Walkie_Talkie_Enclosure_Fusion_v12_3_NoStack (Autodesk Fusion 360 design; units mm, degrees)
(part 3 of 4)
sketch "Volume Up Switch Side Rail Sketch (1)" plane through (0, 0, 0) normal (0, 0, 1) x axis (1, 0, 0)
  line L1 (-32.325, 27.55) -> (-36.675, 27.55)
  line L2 (-32.025, 28.05) -> (-32.025, 27.85)
  line L3 (-36.675, 28.35) -> (-32.325, 28.35)
  line L4 (-36.975, 27.85) -> (-36.975, 28.05)
  arc A1 centre (-32.325, 27.85) radius 0.3 clockwise from (-32.025, 27.85) to (-32.325, 27.55)
  arc A2 centre (-32.325, 28.05) radius 0.3 clockwise from (-32.325, 28.35) to (-32.025, 28.05)
  arc A3 centre (-36.675, 28.05) radius 0.3 clockwise from (-36.975, 28.05) to (-36.675, 28.35)
  arc A4 centre (-36.675, 27.85) radius 0.3 clockwise from (-36.675, 27.55) to (-36.975, 27.85)
extrude "Extrude29" add sketch "Volume Up Switch Side Rail Sketch (1)" blind 7.01 from offset 12
sketch "Volume Up Switch Actuator Shoulder Sketch" plane through (0, 0, 0) normal (0, 0, 1) x axis (1, 0, 0)
  line L1 (-37.22, 17.65) -> (-37.28, 17.65)
  line L2 (-37, 28.13) -> (-37, 17.87)
  line L3 (-37.28, 28.35) -> (-37.22, 28.35)
  line L4 (-37.5, 17.87) -> (-37.5, 28.13)
  arc A1 centre (-37.22, 17.87) radius 0.22 clockwise from (-37, 17.87) to (-37.22, 17.65)
  arc A2 centre (-37.22, 28.13) radius 0.22 clockwise from (-37.22, 28.35) to (-37, 28.13)
  arc A3 centre (-37.28, 28.13) radius 0.22 clockwise from (-37.5, 28.13) to (-37.28, 28.35)
  arc A4 centre (-37.28, 17.87) radius 0.22 clockwise from (-37.28, 17.65) to (-37.5, 17.87)
extrude "Extrude30" add sketch "Volume Up Switch Actuator Shoulder Sketch" blind 7.01 from offset 12
sketch "Volume Up Actuator Passage Sketch" plane through (0, 0, 0) normal (1, 0, 0) x axis (0, 0, -1)
  line L1 (-14.4, 21.6) -> (-16, 21.6)
  line L2 (-13.8, 23.8) -> (-13.8, 22.2)
  line L3 (-16, 24.4) -> (-14.4, 24.4)
  line L4 (-16.6, 22.2) -> (-16.6, 23.8)
  arc A1 centre (-14.4, 22.2) radius 0.6 clockwise from (-13.8, 22.2) to (-14.4, 21.6)
  arc A2 centre (-14.4, 23.8) radius 0.6 clockwise from (-14.4, 24.4) to (-13.8, 23.8)
  arc A3 centre (-16, 23.8) radius 0.6 clockwise from (-16.6, 23.8) to (-16, 24.4)
  arc A4 centre (-16, 22.2) radius 0.6 clockwise from (-16, 21.6) to (-16.6, 22.2)
extrude "Extrude31" cut sketch "Volume Up Actuator Passage Sketch" blind -4.2 (= "-( 4.20 mm )") from offset -35.8
sketch "Volume Down Internal Switch Body Clearance Sketch" plane through (0, 0, 0) normal (1, 0, 0) x axis (0, 0, -1)
  line L1 (-8.49, -11.35) -> (-18.01, -11.35)
  line L2 (-8.04, -1.1) -> (-8.04, -10.9)
  line L3 (-18.01, -0.65) -> (-8.49, -0.65)
  line L4 (-18.46, -10.9) -> (-18.46, -1.1)
  arc A1 centre (-8.49, -10.9) radius 0.45 clockwise from (-8.04, -10.9) to (-8.49, -11.35)
  arc A2 centre (-8.49, -1.1) radius 0.45 clockwise from (-8.49, -0.65) to (-8.04, -1.1)
  arc A3 centre (-18.01, -1.1) radius 0.45 clockwise from (-18.46, -1.1) to (-18.01, -0.65)
  arc A4 centre (-18.01, -10.9) radius 0.45 clockwise from (-18.01, -11.35) to (-18.46, -10.9)
extrude "Extrude32" cut sketch "Volume Down Internal Switch Body Clearance Sketch" blind -5.1 (= "-( 5.10 mm )") from offset -31.9
sketch "Volume Down Switch Cage Anchor Sketch" plane through (0, 0, 0) normal (0, 0, 1) x axis (1, 0, 0)
  line L1 (-31.5, -11.55) -> (-32, -11.55)
  line L2 (-31.15, -10.7) -> (-31.15, -11.2)
  line L3 (-32, -10.35) -> (-31.5, -10.35)
  line L4 (-32.35, -11.2) -> (-32.35, -10.7)
  arc A1 centre (-31.5, -11.2) radius 0.35 clockwise from (-31.15, -11.2) to (-31.5, -11.55)
  arc A2 centre (-31.5, -10.7) radius 0.35 clockwise from (-31.5, -10.35) to (-31.15, -10.7)
  arc A3 centre (-32, -10.7) radius 0.35 clockwise from (-32.35, -10.7) to (-32, -10.35)
  arc A4 centre (-32, -11.2) radius 0.35 clockwise from (-32, -11.55) to (-32.35, -11.2)
extrude "Extrude33" add sketch "Volume Down Switch Cage Anchor Sketch" blind 2.99 from offset 18.91
sketch "Volume Down Switch Cage Anchor Sketch (1)" plane through (0, 0, 0) normal (0, 0, 1) x axis (1, 0, 0)
  line L1 (-31.5, -1.65) -> (-32, -1.65)
  line L2 (-31.15, -0.8) -> (-31.15, -1.3)
  line L3 (-32, -0.45) -> (-31.5, -0.45)
  line L4 (-32.35, -1.3) -> (-32.35, -0.8)
  arc A1 centre (-31.5, -1.3) radius 0.35 clockwise from (-31.15, -1.3) to (-31.5, -1.65)
  arc A2 centre (-31.5, -0.8) radius 0.35 clockwise from (-31.5, -0.45) to (-31.15, -0.8)
  arc A3 centre (-32, -0.8) radius 0.35 clockwise from (-32.35, -0.8) to (-32, -0.45)
  arc A4 centre (-32, -1.3) radius 0.35 clockwise from (-32, -1.65) to (-32.35, -1.3)
extrude "Extrude34" add sketch "Volume Down Switch Cage Anchor Sketch (1)" blind 2.99 from offset 18.91
sketch "Volume Down Switch Roof Sketch" plane through (0, 0, 0) normal (0, 0, 1) x axis (1, 0, 0)
  line L1 (-31.55, -11.35) -> (-36.65, -11.35)
  line L2 (-31.1, -1.1) -> (-31.1, -10.9)
  line L3 (-36.65, -0.65) -> (-31.55, -0.65)
  line L4 (-37.1, -10.9) -> (-37.1, -1.1)
  arc A1 centre (-31.55, -10.9) radius 0.45 clockwise from (-31.1, -10.9) to (-31.55, -11.35)
  arc A2 centre (-31.55, -1.1) radius 0.45 clockwise from (-31.55, -0.65) to (-31.1, -1.1)
  arc A3 centre (-36.65, -1.1) radius 0.45 clockwise from (-37.1, -1.1) to (-36.65, -0.65)
  arc A4 centre (-36.65, -10.9) radius 0.45 clockwise from (-36.65, -11.35) to (-37.1, -10.9)
extrude "Extrude35" add sketch "Volume Down Switch Roof Sketch" blind 0.55 from offset 18.46
sketch "Volume Down Switch Inward Backstop Sketch" plane through (0, 0, 0) normal (0, 0, 1) x axis (1, 0, 0)
  line L1 (-31.65, -11.35) -> (-31.85, -11.35)
  line L2 (-31.3, -1) -> (-31.3, -11)
  line L3 (-31.85, -0.65) -> (-31.65, -0.65)
  line L4 (-32.2, -11) -> (-32.2, -1)
  arc A1 centre (-31.65, -11) radius 0.35 clockwise from (-31.3, -11) to (-31.65, -11.35)
  arc A2 centre (-31.65, -1) radius 0.35 clockwise from (-31.65, -0.65) to (-31.3, -1)
  arc A3 centre (-31.85, -1) radius 0.35 clockwise from (-32.2, -1) to (-31.85, -0.65)
  arc A4 centre (-31.85, -11) radius 0.35 clockwise from (-31.85, -11.35) to (-32.2, -11)
extrude "Extrude36" add sketch "Volume Down Switch Inward Backstop Sketch" blind 7.01 from offset 12
sketch "Volume Down Switch Side Rail Sketch" plane through (0, 0, 0) normal (0, 0, 1) x axis (1, 0, 0)
  line L1 (-32.325, -11.35) -> (-36.675, -11.35)
  line L2 (-32.025, -10.85) -> (-32.025, -11.05)
  line L3 (-36.675, -10.55) -> (-32.325, -10.55)
  line L4 (-36.975, -11.05) -> (-36.975, -10.85)
  arc A1 centre (-32.325, -11.05) radius 0.3 clockwise from (-32.025, -11.05) to (-32.325, -11.35)
  arc A2 centre (-32.325, -10.85) radius 0.3 clockwise from (-32.325, -10.55) to (-32.025, -10.85)
  arc A3 centre (-36.675, -10.85) radius 0.3 clockwise from (-36.975, -10.85) to (-36.675, -10.55)
  arc A4 centre (-36.675, -11.05) radius 0.3 clockwise from (-36.675, -11.35) to (-36.975, -11.05)
extrude "Extrude37" add sketch "Volume Down Switch Side Rail Sketch" blind 7.01 from offset 12
sketch "Volume Down Switch Side Rail Sketch (1)" plane through (0, 0, 0) normal (0, 0, 1) x axis (1, 0, 0)
  line L1 (-32.325, -1.45) -> (-36.675, -1.45)
  line L2 (-32.025, -0.95) -> (-32.025, -1.15)
  line L3 (-36.675, -0.65) -> (-32.325, -0.65)
  line L4 (-36.975, -1.15) -> (-36.975, -0.95)
  arc A1 centre (-32.325, -1.15) radius 0.3 clockwise from (-32.025, -1.15) to (-32.325, -1.45)
  arc A2 centre (-32.325, -0.95) radius 0.3 clockwise from (-32.325, -0.65) to (-32.025, -0.95)
  arc A3 centre (-36.675, -0.95) radius 0.3 clockwise from (-36.975, -0.95) to (-36.675, -0.65)
  arc A4 centre (-36.675, -1.15) radius 0.3 clockwise from (-36.675, -1.45) to (-36.975, -1.15)
extrude "Extrude38" add sketch "Volume Down Switch Side Rail Sketch (1)" blind 7.01 from offset 12
sketch "Volume Down Switch Actuator Shoulder Sketch" plane through (0, 0, 0) normal (0, 0, 1) x axis (1, 0, 0)
  line L1 (-37.22, -11.35) -> (-37.28, -11.35)
  line L2 (-37, -0.87) -> (-37, -11.13)
  line L3 (-37.28, -0.65) -> (-37.22, -0.65)
  line L4 (-37.5, -11.13) -> (-37.5, -0.87)
  arc A1 centre (-37.22, -11.13) radius 0.22 clockwise from (-37, -11.13) to (-37.22, -11.35)
  arc A2 centre (-37.22, -0.87) radius 0.22 clockwise from (-37.22, -0.65) to (-37, -0.87)
  arc A3 centre (-37.28, -0.87) radius 0.22 clockwise from (-37.5, -0.87) to (-37.28, -0.65)
  arc A4 centre (-37.28, -11.13) radius 0.22 clockwise from (-37.28, -11.35) to (-37.5, -11.13)
extrude "Extrude39" add sketch "Volume Down Switch Actuator Shoulder Sketch" blind 7.01 from offset 12
sketch "Volume Down Actuator Passage Sketch" plane through (0, 0, 0) normal (1, 0, 0) x axis (0, 0, -1)
  line L1 (-14.4, -7.4) -> (-16, -7.4)
  line L2 (-13.8, -5.2) -> (-13.8, -6.8)
  line L3 (-16, -4.6) -> (-14.4, -4.6)
  line L4 (-16.6, -6.8) -> (-16.6, -5.2)
  arc A1 centre (-14.4, -6.8) radius 0.6 clockwise from (-13.8, -6.8) to (-14.4, -7.4)
  arc A2 centre (-14.4, -5.2) radius 0.6 clockwise from (-14.4, -4.6) to (-13.8, -5.2)
  arc A3 centre (-16, -5.2) radius 0.6 clockwise from (-16.6, -5.2) to (-16, -4.6)
  arc A4 centre (-16, -6.8) radius 0.6 clockwise from (-16, -7.4) to (-16.6, -6.8)
extrude "Extrude40" cut sketch "Volume Down Actuator Passage Sketch" blind -4.2 (= "-( 4.20 mm )") from offset -35.8
sketch "PCB Rear Edge Clip Trunk Sketch" plane through (0, 0, 0) normal (0, 0, 1) x axis (1, 0, 0)
  line L1 (-30.95, -45.04) -> (-31.65, -45.04)
  line L2 (-30.4, -39.59) -> (-30.4, -44.49)
  line L3 (-31.65, -39.04) -> (-30.95, -39.04)
  line L4 (-32.2, -44.49) -> (-32.2, -39.59)
  arc A1 centre (-30.95, -44.49) radius 0.55 clockwise from (-30.4, -44.49) to (-30.95, -45.04)
  arc A2 centre (-30.95, -39.59) radius 0.55 clockwise from (-30.95, -39.04) to (-30.4, -39.59)
  arc A3 centre (-31.65, -39.59) radius 0.55 clockwise from (-32.2, -39.59) to (-31.65, -39.04)
  arc A4 centre (-31.65, -44.49) radius 0.55 clockwise from (-31.65, -45.04) to (-32.2, -44.49)
extrude "Extrude41" add sketch "PCB Rear Edge Clip Trunk Sketch" blind 7.24 from offset 14.56
sketch "PCB Rear Substrate Ledge Sketch" plane through (0, 0, 0) normal (0, 0, 1) x axis (1, 0, 0)
  line L1 (-28.1, -45.04) -> (-31, -45.04)
  line L2 (-27.45, -39.69) -> (-27.45, -44.39)
  line L3 (-31, -39.04) -> (-28.1, -39.04)
  line L4 (-31.65, -44.39) -> (-31.65, -39.69)
  arc A1 centre (-28.1, -44.39) radius 0.65 clockwise from (-27.45, -44.39) to (-28.1, -45.04)
  arc A2 centre (-28.1, -39.69) radius 0.65 clockwise from (-28.1, -39.04) to (-27.45, -39.69)
  arc A3 centre (-31, -39.69) radius 0.65 clockwise from (-31.65, -39.69) to (-31, -39.04)
  arc A4 centre (-31, -44.39) radius 0.65 clockwise from (-31, -45.04) to (-31.65, -44.39)
extrude "Extrude42" add sketch "PCB Rear Substrate Ledge Sketch" blind 0.45 from offset 14.56
sketch "PCB Rear Edge Clip Trunk Sketch (1)" plane through (0, 0, 0) normal (0, 0, 1) x axis (1, 0, 0)
  line L1 (-30.95, -28.04) -> (-31.65, -28.04)
  line L2 (-30.4, -22.59) -> (-30.4, -27.49)
  line L3 (-31.65, -22.04) -> (-30.95, -22.04)
  line L4 (-32.2, -27.49) -> (-32.2, -22.59)
  arc A1 centre (-30.95, -27.49) radius 0.55 clockwise from (-30.4, -27.49) to (-30.95, -28.04)
  arc A2 centre (-30.95, -22.59) radius 0.55 clockwise from (-30.95, -22.04) to (-30.4, -22.59)
  arc A3 centre (-31.65, -22.59) radius 0.55 clockwise from (-32.2, -22.59) to (-31.65, -22.04)
  arc A4 centre (-31.65, -27.49) radius 0.55 clockwise from (-31.65, -28.04) to (-32.2, -27.49)
extrude "Extrude43" add sketch "PCB Rear Edge Clip Trunk Sketch (1)" blind 7.24 from offset 14.56
sketch "PCB Rear Substrate Ledge Sketch (1)" plane through (0, 0, 0) normal (0, 0, 1) x axis (1, 0, 0)
  line L1 (-28.1, -28.04) -> (-31, -28.04)
  line L2 (-27.45, -22.69) -> (-27.45, -27.39)
  line L3 (-31, -22.04) -> (-28.1, -22.04)
  line L4 (-31.65, -27.39) -> (-31.65, -22.69)
  arc A1 centre (-28.1, -27.39) radius 0.65 clockwise from (-27.45, -27.39) to (-28.1, -28.04)
  arc A2 centre (-28.1, -22.69) radius 0.65 clockwise from (-28.1, -22.04) to (-27.45, -22.69)
  arc A3 centre (-31, -22.69) radius 0.65 clockwise from (-31.65, -22.69) to (-31, -22.04)
  arc A4 centre (-31, -27.39) radius 0.65 clockwise from (-31, -28.04) to (-31.65, -27.39)
extrude "Extrude44" add sketch "PCB Rear Substrate Ledge Sketch (1)" blind 0.45 from offset 14.56
sketch "PCB Rear Edge Clip Trunk Sketch (2)" plane through (0, 0, 0) normal (0, 0, 1) x axis (1, 0, 0)
  line L1 (31.65, -45.04) -> (30.95, -45.04)
  line L2 (32.2, -39.59) -> (32.2, -44.49)
  line L3 (30.95, -39.04) -> (31.65, -39.04)
  line L4 (30.4, -44.49) -> (30.4, -39.59)
  arc A1 centre (31.65, -44.49) radius 0.55 clockwise from (32.2, -44.49) to (31.65, -45.04)
  arc A2 centre (31.65, -39.59) radius 0.55 clockwise from (31.65, -39.04) to (32.2, -39.59)
  arc A3 centre (30.95, -39.59) radius 0.55 clockwise from (30.4, -39.59) to (30.95, -39.04)
  arc A4 centre (30.95, -44.49) radius 0.55 clockwise from (30.95, -45.04) to (30.4, -44.49)
extrude "Extrude45" add sketch "PCB Rear Edge Clip Trunk Sketch (2)" blind 7.24 from offset 14.56
sketch "PCB Rear Substrate Ledge Sketch (2)" plane through (0, 0, 0) normal (0, 0, 1) x axis (1, 0, 0)
  line L1 (31, -45.04) -> (28.1, -45.04)
  line L2 (31.65, -39.69) -> (31.65, -44.39)
  line L3 (28.1, -39.04) -> (31, -39.04)
  line L4 (27.45, -44.39) -> (27.45, -39.69)
  arc A1 centre (31, -44.39) radius 0.65 clockwise from (31.65, -44.39) to (31, -45.04)
  arc A2 centre (31, -39.69) radius 0.65 clockwise from (31, -39.04) to (31.65, -39.69)
  arc A3 centre (28.1, -39.69) radius 0.65 clockwise from (27.45, -39.69) to (28.1, -39.04)
  arc A4 centre (28.1, -44.39) radius 0.65 clockwise from (28.1, -45.04) to (27.45, -44.39)
extrude "Extrude46" add sketch "PCB Rear Substrate Ledge Sketch (2)" blind 0.45 from offset 14.56
sketch "PCB Rear Edge Clip Trunk Sketch (3)" plane through (0, 0, 0) normal (0, 0, 1) x axis (1, 0, 0)
  line L1 (31.65, -28.04) -> (30.95, -28.04)
  line L2 (32.2, -22.59) -> (32.2, -27.49)
  line L3 (30.95, -22.04) -> (31.65, -22.04)
  line L4 (30.4, -27.49) -> (30.4, -22.59)
  arc A1 centre (31.65, -27.49) radius 0.55 clockwise from (32.2, -27.49) to (31.65, -28.04)
  arc A2 centre (31.65, -22.59) radius 0.55 clockwise from (31.65, -22.04) to (32.2, -22.59)
  arc A3 centre (30.95, -22.59) radius 0.55 clockwise from (30.4, -22.59) to (30.95, -22.04)
  arc A4 centre (30.95, -27.49) radius 0.55 clockwise from (30.95, -28.04) to (30.4, -27.49)
extrude "Extrude47" add sketch "PCB Rear Edge Clip Trunk Sketch (3)" blind 7.24 from offset 14.56
sketch "PCB Rear Substrate Ledge Sketch (3)" plane through (0, 0, 0) normal (0, 0, 1) x axis (1, 0, 0)
  line L1 (31, -28.04) -> (28.1, -28.04)
  line L2 (31.65, -22.69) -> (31.65, -27.39)
  line L3 (28.1, -22.04) -> (31, -22.04)
  line L4 (27.45, -27.39) -> (27.45, -22.69)
  arc A1 centre (31, -27.39) radius 0.65 clockwise from (31.65, -27.39) to (31, -28.04)
  arc A2 centre (31, -22.69) radius 0.65 clockwise from (31, -22.04) to (31.65, -22.69)
  arc A3 centre (28.1, -22.69) radius 0.65 clockwise from (27.45, -22.69) to (28.1, -22.04)
  arc A4 centre (28.1, -27.39) radius 0.65 clockwise from (28.1, -28.04) to (27.45, -27.39)
extrude "Extrude48" add sketch "PCB Rear Substrate Ledge Sketch (3)" blind 0.45 from offset 14.56
sketch "USB-C Metal-Shell Insertion Reaction Bridge Sketch" plane through (0, 0, 0) normal (0, 0, 1) x axis (1, 0, 0)
  line L1 (21.7273, -45.5243) -> (20.6273, -45.5243)
  line L2 (22.2773, -37.1343) -> (22.2773, -44.9743)
  line L3 (20.6273, -36.5843) -> (21.7273, -36.5843)
  line L4 (20.0773, -44.9743) -> (20.0773, -37.1343)
  arc A1 centre (21.7273, -44.9743) radius 0.55 clockwise from (22.2773, -44.9743) to (21.7273, -45.5243)
  arc A2 centre (21.7273, -37.1343) radius 0.55 clockwise from (21.7273, -36.5843) to (22.2773, -37.1343)
  arc A3 centre (20.6273, -37.1343) radius 0.55 clockwise from (20.0773, -37.1343) to (20.6273, -36.5843)
  arc A4 centre (20.6273, -44.9743) radius 0.55 clockwise from (20.6273, -45.5243) to (20.0773, -44.9743)
extrude "Extrude49" add sketch "USB-C Metal-Shell Insertion Reaction Bridge Sketch" blind 7.1901 from offset 14.7099
sketch "PCB Rear-Wall Lower Y Stop Sketch" plane through (0, 0, 0) normal (0, 0, 1) x axis (1, 0, 0)
  line L1 (-21.45, -54.7) -> (-32.55, -54.7)
  line L2 (-21, -53.75) -> (-21, -54.25)
  line L3 (-32.55, -53.3) -> (-21.45, -53.3)
  line L4 (-33, -54.25) -> (-33, -53.75)
  arc A1 centre (-21.45, -54.25) radius 0.45 clockwise from (-21, -54.25) to (-21.45, -54.7)
  arc A2 centre (-21.45, -53.75) radius 0.45 clockwise from (-21.45, -53.3) to (-21, -53.75)
  arc A3 centre (-32.55, -53.75) radius 0.45 clockwise from (-33, -53.75) to (-32.55, -53.3)
  arc A4 centre (-32.55, -54.25) radius 0.45 clockwise from (-32.55, -54.7) to (-33, -54.25)
extrude "Extrude50" add sketch "PCB Rear-Wall Lower Y Stop Sketch" blind 9.7 from offset 12.2
sketch "PCB Rear-Wall Lower Y Stop Sketch (1)" plane through (0, 0, 0) normal (0, 0, 1) x axis (1, 0, 0)
  line L1 (32.55, -54.7) -> (21.45, -54.7)
  line L2 (33, -53.75) -> (33, -54.25)
  line L3 (21.45, -53.3) -> (32.55, -53.3)
  line L4 (21, -54.25) -> (21, -53.75)
  arc A1 centre (32.55, -54.25) radius 0.45 clockwise from (33, -54.25) to (32.55, -54.7)
  arc A2 centre (32.55, -53.75) radius 0.45 clockwise from (32.55, -53.3) to (33, -53.75)
  arc A3 centre (21.45, -53.75) radius 0.45 clockwise from (21, -53.75) to (21.45, -53.3)
  arc A4 centre (21.45, -54.25) radius 0.45 clockwise from (21.45, -54.7) to (21, -54.25)
extrude "Extrude51" add sketch "PCB Rear-Wall Lower Y Stop Sketch (1)" blind 9.7 from offset 12.2
sketch "Battery Cradle Left Side Rail Sketch" plane through (0, 0, 0) normal (0, 0, 1) x axis (1, 0, 0)
  line L1 (-30.86, 28.02) -> (-31.06, 28.02)
  line L2 (-30.26, 63.94) -> (-30.26, 28.62)
  line L3 (-31.06, 64.54) -> (-30.86, 64.54)
  line L4 (-31.66, 28.62) -> (-31.66, 63.94)
  arc A1 centre (-30.86, 28.62) radius 0.6 clockwise from (-30.26, 28.62) to (-30.86, 28.02)
  arc A2 centre (-30.86, 63.94) radius 0.6 clockwise from (-30.86, 64.54) to (-30.26, 63.94)
  arc A3 centre (-31.06, 63.94) radius 0.6 clockwise from (-31.66, 63.94) to (-31.06, 64.54)
  arc A4 centre (-31.06, 28.62) radius 0.6 clockwise from (-31.06, 28.02) to (-31.66, 28.62)
extrude "Extrude52" add sketch "Battery Cradle Left Side Rail Sketch" blind 4.82 from offset 12
sketch "Battery +X Lead-Relieved Side Rail Sketch" plane through (0, 0, 0) normal (0, 0, 1) x axis (1, 0, 0)
  line L1 (31.06, 28.02) -> (30.86, 28.02)
  line L2 (31.66, 43.03) -> (31.66, 28.62)
  line L3 (30.86, 43.63) -> (31.06, 43.63)
  line L4 (30.26, 28.62) -> (30.26, 43.03)
  arc A1 centre (31.06, 28.62) radius 0.6 clockwise from (31.66, 28.62) to (31.06, 28.02)
  arc A2 centre (31.06, 43.03) radius 0.6 clockwise from (31.06, 43.63) to (31.66, 43.03)
  arc A3 centre (30.86, 43.03) radius 0.6 clockwise from (30.26, 43.03) to (30.86, 43.63)
  arc A4 centre (30.86, 28.62) radius 0.6 clockwise from (30.86, 28.02) to (30.26, 28.62)
extrude "Extrude53" new body sketch "Battery +X Lead-Relieved Side Rail Sketch" blind 4.82 from offset 12
sketch "Battery +X Lead-Relieved Side Rail Sketch (1)" plane through (0, 0, 0) normal (0, 0, 1) x axis (1, 0, 0)
  line L1 (31.06, 48.93) -> (30.86, 48.93)
  line L2 (31.66, 63.94) -> (31.66, 49.53)
  line L3 (30.86, 64.54) -> (31.06, 64.54)
  line L4 (30.26, 49.53) -> (30.26, 63.94)
  arc A1 centre (31.06, 49.53) radius 0.6 clockwise from (31.66, 49.53) to (31.06, 48.93)
  arc A2 centre (31.06, 63.94) radius 0.6 clockwise from (31.06, 64.54) to (31.66, 63.94)
  arc A3 centre (30.86, 63.94) radius 0.6 clockwise from (30.26, 63.94) to (30.86, 64.54)
  arc A4 centre (30.86, 49.53) radius 0.6 clockwise from (30.86, 48.93) to (30.26, 49.53)
extrude "Extrude54" add sketch "Battery +X Lead-Relieved Side Rail Sketch (1)" blind 4.82 from offset 12
sketch "No-Stack PCB-Battery Shared Divider Sketch" plane through (0, 0, 0) normal (0, 0, 1) x axis (1, 0, 0)
  line L1 (31.45, 27.22) -> (-31.45, 27.22)
  line L2 (31.8, 27.67) -> (31.8, 27.57)
  line L3 (-31.45, 28.02) -> (31.45, 28.02)
  line L4 (-31.8, 27.57) -> (-31.8, 27.67)
  arc A1 centre (31.45, 27.57) radius 0.35 clockwise from (31.8, 27.57) to (31.45, 27.22)
  arc A2 centre (31.45, 27.67) radius 0.35 clockwise from (31.45, 28.02) to (31.8, 27.67)
  arc A3 centre (-31.45, 27.67) radius 0.35 clockwise from (-31.8, 27.67) to (-31.45, 28.02)
  arc A4 centre (-31.45, 27.57) radius 0.35 clockwise from (-31.45, 27.22) to (-31.8, 27.57)
extrude "Extrude55" add sketch "No-Stack PCB-Battery Shared Divider Sketch" blind 4.82 from offset 12
sketch "Battery Cradle Top Rail Sketch" plane through (0, 0, 0) normal (0, 0, 1) x axis (1, 0, 0)
  line L1 (31.2, 64.54) -> (-31.2, 64.54)
  line L2 (31.8, 65.34) -> (31.8, 65.14)
  line L3 (-31.2, 65.94) -> (31.2, 65.94)
  line L4 (-31.8, 65.14) -> (-31.8, 65.34)
  arc A1 centre (31.2, 65.14) radius 0.6 clockwise from (31.8, 65.14) to (31.2, 64.54)
  arc A2 centre (31.2, 65.34) radius 0.6 clockwise from (31.2, 65.94) to (31.8, 65.34)
  arc A3 centre (-31.2, 65.34) radius 0.6 clockwise from (-31.8, 65.34) to (-31.2, 65.94)
  arc A4 centre (-31.2, 65.14) radius 0.6 clockwise from (-31.2, 64.54) to (-31.8, 65.14)
extrude "Extrude56" add sketch "Battery Cradle Top Rail Sketch" blind 4.82 from offset 12
sketch "Battery Service-Removal Relief Sketch" plane through (0, 0, 0) normal (0, 0, 1) x axis (1, 0, 0)
  line L1 (9.25, 64.24) -> (-9.25, 64.24)
  line L2 (10, 65.49) -> (10, 64.99)
  line L3 (-9.25, 66.24) -> (9.25, 66.24)
  line L4 (-10, 64.99) -> (-10, 65.49)
  arc A1 centre (9.25, 64.99) radius 0.75 clockwise from (10, 64.99) to (9.25, 64.24)
  arc A2 centre (9.25, 65.49) radius 0.75 clockwise from (9.25, 66.24) to (10, 65.49)
  arc A3 centre (-9.25, 65.49) radius 0.75 clockwise from (-10, 65.49) to (-9.25, 66.24)
  arc A4 centre (-9.25, 64.99) radius 0.75 clockwise from (-9.25, 64.24) to (-10, 64.99)
extrude "Extrude57" cut sketch "Battery Service-Removal Relief Sketch" blind 5.02 from offset 11.9
sketch "Battery Broad Rear Retention Pad Sketch" plane through (0, 0, 0) normal (0, 0, 1) x axis (1, 0, 0)
  line L1 (-22, 42.28) -> (-26, 42.28)
  line L2 (-20, 48.28) -> (-20, 44.28)
  line L3 (-26, 50.28) -> (-22, 50.28)
  line L4 (-28, 44.28) -> (-28, 48.28)
  arc A1 centre (-22, 44.28) radius 2 clockwise from (-20, 44.28) to (-22, 42.28)
  arc A2 centre (-22, 48.28) radius 2 clockwise from (-22, 50.28) to (-20, 48.28)
  arc A3 centre (-26, 48.28) radius 2 clockwise from (-28, 48.28) to (-26, 50.28)
  arc A4 centre (-26, 44.28) radius 2 clockwise from (-26, 42.28) to (-28, 44.28)
extrude "Extrude58" add sketch "Battery Broad Rear Retention Pad Sketch" blind 4.98 from offset 16.82
sketch "Battery Soft-Pad Location Pocket Sketch" plane through (0, 0, 0) normal (0, 0, 1) x axis (1, 0, 0)
  line L1 (-22.5, 43.28) -> (-25.5, 43.28)
  line L2 (-21, 47.78) -> (-21, 44.78)
  line L3 (-25.5, 49.28) -> (-22.5, 49.28)
  line L4 (-27, 44.78) -> (-27, 47.78)
  arc A1 centre (-22.5, 44.78) radius 1.5 clockwise from (-21, 44.78) to (-22.5, 43.28)
  arc A2 centre (-22.5, 47.78) radius 1.5 clockwise from (-22.5, 49.28) to (-21, 47.78)
  arc A3 centre (-25.5, 47.78) radius 1.5 clockwise from (-27, 47.78) to (-25.5, 49.28)
  arc A4 centre (-25.5, 44.78) radius 1.5 clockwise from (-25.5, 43.28) to (-27, 44.78)
extrude "Extrude59" cut sketch "Battery Soft-Pad Location Pocket Sketch" blind 0.5 from offset 16.77
sketch "Battery Broad Rear Retention Pad Sketch (1)" plane through (0, 0, 0) normal (0, 0, 1) x axis (1, 0, 0)
  line L1 (26, 42.28) -> (22, 42.28)
  line L2 (28, 48.28) -> (28, 44.28)
  line L3 (22, 50.28) -> (26, 50.28)
  line L4 (20, 44.28) -> (20, 48.28)
  arc A1 centre (26, 44.28) radius 2 clockwise from (28, 44.28) to (26, 42.28)
  arc A2 centre (26, 48.28) radius 2 clockwise from (26, 50.28) to (28, 48.28)
  arc A3 centre (22, 48.28) radius 2 clockwise from (20, 48.28) to (22, 50.28)
  arc A4 centre (22, 44.28) radius 2 clockwise from (22, 42.28) to (20, 44.28)
extrude "Extrude60" add sketch "Battery Broad Rear Retention Pad Sketch (1)" blind 4.98 from offset 16.82
sketch "Battery Soft-Pad Location Pocket Sketch (1)" plane through (0, 0, 0) normal (0, 0, 1) x axis (1, 0, 0)
  line L1 (25.5, 43.28) -> (22.5, 43.28)
  line L2 (27, 47.78) -> (27, 44.78)
  line L3 (22.5, 49.28) -> (25.5, 49.28)
  line L4 (21, 44.78) -> (21, 47.78)
  arc A1 centre (25.5, 44.78) radius 1.5 clockwise from (27, 44.78) to (25.5, 43.28)
  arc A2 centre (25.5, 47.78) radius 1.5 clockwise from (25.5, 49.28) to (27, 47.78)
  arc A3 centre (22.5, 47.78) radius 1.5 clockwise from (21, 47.78) to (22.5, 49.28)
  arc A4 centre (22.5, 44.78) radius 1.5 clockwise from (22.5, 43.28) to (21, 44.78)
extrude "Extrude61" cut sketch "Battery Soft-Pad Location Pocket Sketch (1)" blind 0.5 from offset 16.77
sketch "LTE Antenna Locator Rail Sketch" plane through (0, 0, 0) normal (0, 0, 1) x axis (1, 0, 0)
  line L1 (-11.16, -34.76) -> (-11.26, -34.76)
  line L2 (-10.76, 67.36) -> (-10.76, -34.36)
  line L3 (-11.26, 67.76) -> (-11.16, 67.76)
  line L4 (-11.66, -34.36) -> (-11.66, 67.36)
  arc A1 centre (-11.16, -34.36) radius 0.4 clockwise from (-10.76, -34.36) to (-11.16, -34.76)
  arc A2 centre (-11.16, 67.36) radius 0.4 clockwise from (-11.16, 67.76) to (-10.76, 67.36)
  arc A3 centre (-11.26, 67.36) radius 0.4 clockwise from (-11.66, 67.36) to (-11.26, 67.76)
  arc A4 centre (-11.26, -34.36) radius 0.4 clockwise from (-11.26, -34.76) to (-11.66, -34.36)
extrude "Extrude62" add sketch "LTE Antenna Locator Rail Sketch" blind 1.28 from offset 20.52
sketch "LTE Antenna Locator Rail Sketch (1)" plane through (0, 0, 0) normal (0, 0, 1) x axis (1, 0, 0)
  line L1 (11.26, -34.76) -> (11.16, -34.76)
  line L2 (11.66, 67.36) -> (11.66, -34.36)
  line L3 (11.16, 67.76) -> (11.26, 67.76)
  line L4 (10.76, -34.36) -> (10.76, 67.36)
  arc A1 centre (11.26, -34.36) radius 0.4 clockwise from (11.66, -34.36) to (11.26, -34.76)
  arc A2 centre (11.26, 67.36) radius 0.4 clockwise from (11.26, 67.76) to (11.66, 67.36)
  arc A3 centre (11.16, 67.36) radius 0.4 clockwise from (10.76, 67.36) to (11.16, 67.76)
  arc A4 centre (11.16, -34.36) radius 0.4 clockwise from (11.16, -34.76) to (10.76, -34.36)
extrude "Extrude63" add sketch "LTE Antenna Locator Rail Sketch (1)" blind 1.28 from offset 20.52
sketch "LTE Antenna Lower End Stop Sketch" plane through (0, 0, 0) normal (0, 0, 1) x axis (1, 0, 0)
  line L1 (11.1, -35.66) -> (-11.1, -35.66)
  line L2 (11.5, -35.16) -> (11.5, -35.26)
  line L3 (-11.1, -34.76) -> (11.1, -34.76)
  line L4 (-11.5, -35.26) -> (-11.5, -35.16)
  arc A1 centre (11.1, -35.26) radius 0.4 clockwise from (11.5, -35.26) to (11.1, -35.66)
  arc A2 centre (11.1, -35.16) radius 0.4 clockwise from (11.1, -34.76) to (11.5, -35.16)
  arc A3 centre (-11.1, -35.16) radius 0.4 clockwise from (-11.5, -35.16) to (-11.1, -34.76)
  arc A4 centre (-11.1, -35.26) radius 0.4 clockwise from (-11.1, -35.66) to (-11.5, -35.26)
extrude "Extrude64" add sketch "LTE Antenna Lower End Stop Sketch" blind 1.28 from offset 20.52
sketch "Sketch65" plane through (0, 0, 0) normal (0, 0, 1) x axis (1, 0, 0)
  line L1 (-5.4, 67.76) -> (-11.1, 67.76)
  line L2 (-5, 68.26) -> (-5, 68.16)
  line L3 (-11.1, 68.66) -> (-5.4, 68.66)
  line L4 (-11.5, 68.16) -> (-11.5, 68.26)
  arc A1 centre (-5.4, 68.16) radius 0.4 clockwise from (-5, 68.16) to (-5.4, 67.76)
  arc A2 centre (-5.4, 68.26) radius 0.4 clockwise from (-5.4, 68.66) to (-5, 68.26)
  arc A3 centre (-11.1, 68.26) radius 0.4 clockwise from (-11.5, 68.26) to (-11.1, 68.66)
  arc A4 centre (-11.1, 68.16) radius 0.4 clockwise from (-11.1, 67.76) to (-11.5, 68.16)
extrude "Extrude65" add sketch "Sketch65" blind 1.28 from offset 20.52
sketch "Sketch66" plane through (0, 0, 0) normal (0, 0, 1) x axis (1, 0, 0)
  line L1 (11.1, 67.76) -> (5.4, 67.76)
  line L2 (11.5, 68.26) -> (11.5, 68.16)
  line L3 (5.4, 68.66) -> (11.1, 68.66)
  line L4 (5, 68.16) -> (5, 68.26)
  arc A1 centre (11.1, 68.16) radius 0.4 clockwise from (11.5, 68.16) to (11.1, 67.76)
  arc A2 centre (11.1, 68.26) radius 0.4 clockwise from (11.1, 68.66) to (11.5, 68.26)
  arc A3 centre (5.4, 68.26) radius 0.4 clockwise from (5, 68.26) to (5.4, 68.66)
  arc A4 centre (5.4, 68.16) radius 0.4 clockwise from (5.4, 67.76) to (5, 68.16)
extrude "Extrude66" add sketch "Sketch66" blind 1.28 from offset 20.52
sketch "LTE Antenna Front Capture Lip Sketch" plane through (0, 0, 0) normal (0, 0, 1) x axis (1, 0, 0)
  line L1 (-9.85, -22) -> (-10.95, -22)
  line L2 (-9.4, -18.45) -> (-9.4, -21.55)
  line L3 (-10.95, -18) -> (-9.85, -18)
  line L4 (-11.4, -21.55) -> (-11.4, -18.45)
  arc A1 centre (-9.85, -21.55) radius 0.45 clockwise from (-9.4, -21.55) to (-9.85, -22)
  arc A2 centre (-9.85, -18.45) radius 0.45 clockwise from (-9.85, -18) to (-9.4, -18.45)
  arc A3 centre (-10.95, -18.45) radius 0.45 clockwise from (-11.4, -18.45) to (-10.95, -18)
  arc A4 centre (-10.95, -21.55) radius 0.45 clockwise from (-10.95, -22) to (-11.4, -21.55)
extrude "Extrude67" add sketch "LTE Antenna Front Capture Lip Sketch" blind 0.2 from offset 20.47
sketch "LTE Antenna Front Capture Lip Sketch (1)" plane through (0, 0, 0) normal (0, 0, 1) x axis (1, 0, 0)
  line L1 (-9.85, 51) -> (-10.95, 51)
  line L2 (-9.4, 54.55) -> (-9.4, 51.45)
  line L3 (-10.95, 55) -> (-9.85, 55)
  line L4 (-11.4, 51.45) -> (-11.4, 54.55)
  arc A1 centre (-9.85, 51.45) radius 0.45 clockwise from (-9.4, 51.45) to (-9.85, 51)
  arc A2 centre (-9.85, 54.55) radius 0.45 clockwise from (-9.85, 55) to (-9.4, 54.55)
  arc A3 centre (-10.95, 54.55) radius 0.45 clockwise from (-11.4, 54.55) to (-10.95, 55)
  arc A4 centre (-10.95, 51.45) radius 0.45 clockwise from (-10.95, 51) to (-11.4, 51.45)
extrude "Extrude68" add sketch "LTE Antenna Front Capture Lip Sketch (1)" blind 0.2 from offset 20.47
sketch "LTE Antenna Front Capture Lip Sketch (2)" plane through (0, 0, 0) normal (0, 0, 1) x axis (1, 0, 0)
  line L1 (10.95, -22) -> (9.85, -22)
  line L2 (11.4, -18.45) -> (11.4, -21.55)
  line L3 (9.85, -18) -> (10.95, -18)
  line L4 (9.4, -21.55) -> (9.4, -18.45)
  arc A1 centre (10.95, -21.55) radius 0.45 clockwise from (11.4, -21.55) to (10.95, -22)
  arc A2 centre (10.95, -18.45) radius 0.45 clockwise from (10.95, -18) to (11.4, -18.45)
  arc A3 centre (9.85, -18.45) radius 0.45 clockwise from (9.4, -18.45) to (9.85, -18)
  arc A4 centre (9.85, -21.55) radius 0.45 clockwise from (9.85, -22) to (9.4, -21.55)
extrude "Extrude69" add sketch "LTE Antenna Front Capture Lip Sketch (2)" blind 0.2 from offset 20.47
sketch "LTE Antenna Front Capture Lip Sketch (3)" plane through (0, 0, 0) normal (0, 0, 1) x axis (1, 0, 0)
  line L1 (10.95, 51) -> (9.85, 51)
  line L2 (11.4, 54.55) -> (11.4, 51.45)
  line L3 (9.85, 55) -> (10.95, 55)
  line L4 (9.4, 51.45) -> (9.4, 54.55)
  arc A1 centre (10.95, 51.45) radius 0.45 clockwise from (11.4, 51.45) to (10.95, 51)
  arc A2 centre (10.95, 54.55) radius 0.45 clockwise from (10.95, 55) to (11.4, 54.55)
  arc A3 centre (9.85, 54.55) radius 0.45 clockwise from (9.4, 54.55) to (9.85, 55)
  arc A4 centre (9.85, 51.45) radius 0.45 clockwise from (9.85, 51) to (9.4, 51.45)
extrude "Extrude70" add sketch "LTE Antenna Front Capture Lip Sketch (3)" blind 0.2 from offset 20.47
sketch "LTE Antenna Rear Land Sketch" plane through (0, 0, 0) normal (0, 0, 1) x axis (1, 0, 0)
  line L1 (-8.45, -22) -> (-9.55, -22)
  line L2 (-8, -18.45) -> (-8, -21.55)
  line L3 (-9.55, -18) -> (-8.45, -18)
  line L4 (-10, -21.55) -> (-10, -18.45)
  arc A1 centre (-8.45, -21.55) radius 0.45 clockwise from (-8, -21.55) to (-8.45, -22)
  arc A2 centre (-8.45, -18.45) radius 0.45 clockwise from (-8.45, -18) to (-8, -18.45)
  arc A3 centre (-9.55, -18.45) radius 0.45 clockwise from (-10, -18.45) to (-9.55, -18)
  arc A4 centre (-9.55, -21.55) radius 0.45 clockwise from (-9.55, -22) to (-10, -21.55)
extrude "Extrude71" add sketch "LTE Antenna Rear Land Sketch" blind 0.26 from offset 21.54
sketch "LTE Antenna Rear Land Sketch (1)" plane through (0, 0, 0) normal (0, 0, 1) x axis (1, 0, 0)
  line L1 (-8.45, 51) -> (-9.55, 51)
  line L2 (-8, 54.55) -> (-8, 51.45)
  line L3 (-9.55, 55) -> (-8.45, 55)
  line L4 (-10, 51.45) -> (-10, 54.55)
  arc A1 centre (-8.45, 51.45) radius 0.45 clockwise from (-8, 51.45) to (-8.45, 51)
  arc A2 centre (-8.45, 54.55) radius 0.45 clockwise from (-8.45, 55) to (-8, 54.55)
  arc A3 centre (-9.55, 54.55) radius 0.45 clockwise from (-10, 54.55) to (-9.55, 55)
  arc A4 centre (-9.55, 51.45) radius 0.45 clockwise from (-9.55, 51) to (-10, 51.45)
extrude "Extrude72" add sketch "LTE Antenna Rear Land Sketch (1)" blind 0.26 from offset 21.54
sketch "LTE Antenna Rear Land Sketch (2)" plane through (0, 0, 0) normal (0, 0, 1) x axis (1, 0, 0)
  line L1 (9.55, -22) -> (8.45, -22)
  line L2 (10, -18.45) -> (10, -21.55)
  line L3 (8.45, -18) -> (9.55, -18)
  line L4 (8, -21.55) -> (8, -18.45)
  arc A1 centre (9.55, -21.55) radius 0.45 clockwise from (10, -21.55) to (9.55, -22)
  arc A2 centre (9.55, -18.45) radius 0.45 clockwise from (9.55, -18) to (10, -18.45)
  arc A3 centre (8.45, -18.45) radius 0.45 clockwise from (8, -18.45) to (8.45, -18)
  arc A4 centre (8.45, -21.55) radius 0.45 clockwise from (8.45, -22) to (8, -21.55)
extrude "Extrude73" add sketch "LTE Antenna Rear Land Sketch (2)" blind 0.26 from offset 21.54
sketch "LTE Antenna Rear Land Sketch (3)" plane through (0, 0, 0) normal (0, 0, 1) x axis (1, 0, 0)
  line L1 (9.55, 51) -> (8.45, 51)
  line L2 (10, 54.55) -> (10, 51.45)
  line L3 (8.45, 55) -> (9.55, 55)
  line L4 (8, 51.45) -> (8, 54.55)
  arc A1 centre (9.55, 51.45) radius 0.45 clockwise from (10, 51.45) to (9.55, 51)
  arc A2 centre (9.55, 54.55) radius 0.45 clockwise from (9.55, 55) to (10, 54.55)
  arc A3 centre (8.45, 54.55) radius 0.45 clockwise from (8, 54.55) to (8.45, 55)
  arc A4 centre (8.45, 51.45) radius 0.45 clockwise from (8.45, 51) to (8, 51.45)
extrude "Extrude74" add sketch "LTE Antenna Rear Land Sketch (3)" blind 0.26 from offset 21.54
sketch "Rear Screw Bosses" plane through (0, 0, 0) normal (0, 0, 1) x axis (1, 0, 0)
  circle C1 centre (-33.4, -56) radius 2.8
  circle C2 centre (-33.4, 56) radius 2.8
  circle C3 centre (33.4, -56) radius 2.8
  circle C4 centre (33.4, 56) radius 2.8
extrude "Extrude75" add sketch "Rear Screw Bosses" blind 2 from offset 12
sketch "M2.5 Screw Clearances" plane through (0, 0, 0) normal (0, 0, 1) x axis (1, 0, 0)
  circle C1 centre (-33.4, -56) radius 1.45
  circle C2 centre (-33.4, 56) radius 1.45
  circle C3 centre (33.4, -56) radius 1.45
  circle C4 centre (33.4, 56) radius 1.45
extrude "Extrude76" cut sketch "M2.5 Screw Clearances" blind 13 from offset 11.5
sketch "Rear Screw Counterbores" plane through (0, 0, 0) normal (0, 0, 1) x axis (1, 0, 0)
  circle C1 centre (-33.4, -56) radius 2.55
  circle C2 centre (-33.4, 56) radius 2.55
  circle C3 centre (33.4, -56) radius 2.55
  circle C4 centre (33.4, 56) radius 2.55
extrude "Extrude77" cut sketch "Rear Screw Counterbores" blind 3.3 from offset 21.2
sketch "Quiet Orb Action Button Cap Sketch" plane through (0, 0, 0) normal (0, 0, 1) x axis (1, 0, 0)
  line L1 (4.4, -60.7) -> (-4.4, -60.7)
  line L2 (13.7, -42.6) -> (13.7, -51.4)
  line L3 (-4.4, -33.3) -> (4.4, -33.3)
  line L4 (-13.7, -51.4) -> (-13.7, -42.6)
  arc A1 centre (4.4, -51.4) radius 9.3 clockwise from (13.7, -51.4) to (4.4, -60.7)
  arc A2 centre (4.4, -42.6) radius 9.3 clockwise from (4.4, -33.3) to (13.7, -42.6)
  arc A3 centre (-4.4, -42.6) radius 9.3 clockwise from (-13.7, -42.6) to (-4.4, -33.3)
  arc A4 centre (-4.4, -51.4) radius 9.3 clockwise from (-4.4, -60.7) to (-13.7, -51.4)
extrude "Extrude1" new body sketch "Quiet Orb Action Button Cap Sketch" blind 2.95 from offset -0.55
fillet "Fillet1" radius 1.35
sketch "Action Button Guide Ring" plane through (0, 0, 0) normal (0, 0, 1) x axis (1, 0, 0)
  line L1 (4.3, -60.5) -> (-4.3, -60.5)
  line L2 (13.5, -42.7) -> (13.5, -51.3)
  line L3 (-4.3, -33.5) -> (4.3, -33.5)
  line L4 (-13.5, -51.3) -> (-13.5, -42.7)
  line L5 (4.55, -58.8) -> (-4.55, -58.8)
  line L6 (11.8, -42.45) -> (11.8, -51.55)
  line L7 (-4.55, -35.2) -> (4.55, -35.2)
  line L8 (-11.8, -51.55) -> (-11.8, -42.45)
  arc A1 centre (4.3, -51.3) radius 9.2 clockwise from (13.5, -51.3) to (4.3, -60.5)
  arc A2 centre (4.3, -42.7) radius 9.2 clockwise from (4.3, -33.5) to (13.5, -42.7)
  arc A3 centre (-4.3, -42.7) radius 9.2 clockwise from (-13.5, -42.7) to (-4.3, -33.5)
  arc A4 centre (-4.3, -51.3) radius 9.2 clockwise from (-4.3, -60.5) to (-13.5, -51.3)
  arc A5 centre (4.55, -51.55) radius 7.25 clockwise from (11.8, -51.55) to (4.55, -58.8)
  arc A6 centre (4.55, -42.45) radius 7.25 clockwise from (4.55, -35.2) to (11.8, -42.45)
  arc A7 centre (-4.55, -42.45) radius 7.25 clockwise from (-11.8, -42.45) to (-4.55, -35.2)
  arc A8 centre (-4.55, -51.55) radius 7.25 clockwise from (-4.55, -58.8) to (-11.8, -51.55)
extrude "Extrude2" add sketch "Action Button Guide Ring" blind 0.5 from offset 1.8
sketch "Action Button Captive Retention Tab Sketch" plane through (0, 0, 0) normal (0, 0, 1) x axis (1, 0, 0)
  line L1 (13.5, -61.2) -> (-13.5, -61.2)
  line L2 (14.5, -59.8) -> (14.5, -60.2)
  line L3 (-13.5, -58.8) -> (13.5, -58.8)
  line L4 (-14.5, -60.2) -> (-14.5, -59.8)
  arc A1 centre (13.5, -60.2) radius 1 clockwise from (14.5, -60.2) to (13.5, -61.2)
  arc A2 centre (13.5, -59.8) radius 1 clockwise from (13.5, -58.8) to (14.5, -59.8)
  arc A3 centre (-13.5, -59.8) radius 1 clockwise from (-14.5, -59.8) to (-13.5, -58.8)
  arc A4 centre (-13.5, -60.2) radius 1 clockwise from (-13.5, -61.2) to (-14.5, -60.2)
extrude "Extrude3" add sketch "Action Button Captive Retention Tab Sketch" blind 0.5 from offset 2.3
sketch "Action Button Captive Retention Tab Sketch (1)" plane through (0, 0, 0) normal (0, 0, 1) x axis (1, 0, 0)
  line L1 (13.5, -35.2) -> (-13.5, -35.2)
  line L2 (14.5, -33.8) -> (14.5, -34.2)
  line L3 (-13.5, -32.8) -> (13.5, -32.8)
  line L4 (-14.5, -34.2) -> (-14.5, -33.8)
  arc A1 centre (13.5, -34.2) radius 1 clockwise from (14.5, -34.2) to (13.5, -35.2)
  arc A2 centre (13.5, -33.8) radius 1 clockwise from (13.5, -32.8) to (14.5, -33.8)
  arc A3 centre (-13.5, -33.8) radius 1 clockwise from (-14.5, -33.8) to (-13.5, -32.8)
  arc A4 centre (-13.5, -34.2) radius 1 clockwise from (-13.5, -35.2) to (-14.5, -34.2)
extrude "Extrude4" add sketch "Action Button Captive Retention Tab Sketch (1)" blind 0.5 from offset 2.3
sketch "Sketch5" plane through (0, 0, 0) normal (0, 0, 1) x axis (1, 0, 0)
  circle C1 centre (0, -47) radius 2.5
extrude "Extrude5" add sketch "Sketch5" blind 0.4 from offset 2.25
sketch "Raised Action Mark" plane through (0, 0, 0) normal (0, 0, 1) x axis (1, 0, 0)
  line L1 (3.4, -42.8) -> (3.4, -51.2)
  line L2 (-4.2, -47) -> (3.4, -42.8)
  line L3 (3.4, -51.2) -> (-4.2, -47)
extrude "Extrude6" cut sketch "Raised Action Mark" blind 0.42 from offset -0.6
sketch "Status Light Diffuser Sketch" plane through (0, 0, 0) normal (0, 0, 1) x axis (1, 0, 0)
  line L1 (0.05, 0.1) -> (-0.05, 0.1)
  line L2 (1.9, 8.05) -> (1.9, 1.95)
  line L3 (-0.05, 9.9) -> (0.05, 9.9)
  line L4 (-1.9, 1.95) -> (-1.9, 8.05)
  arc A1 centre (0.05, 1.95) radius 1.85 clockwise from (1.9, 1.95) to (0.05, 0.1)
  arc A2 centre (0.05, 8.05) radius 1.85 clockwise from (0.05, 9.9) to (1.9, 8.05)
  arc A3 centre (-0.05, 8.05) radius 1.85 clockwise from (-1.9, 8.05) to (-0.05, 9.9)
  arc A4 centre (-0.05, 1.95) radius 1.85 clockwise from (-0.05, 0.1) to (-1.9, 1.95)
extrude "Extrude1" new body sketch "Status Light Diffuser Sketch" blind 2.82 from offset -0.42
fillet "Fillet1" radius 0.65
sketch "Status Light Collector Sketch" plane through (0, 0, 0) normal (0, 0, 1) x axis (1, 0, 0)
  circle C1 centre (0, 5) radius 2.7
extrude "Extrude2" add sketch "Status Light Collector Sketch" blind 1.35 from offset 2.15
sketch "Front Switch Clamp Plate Sketch" plane through (0, 0, 0) normal (0, 0, 1) x axis (1, 0, 0)
  line L1 (17, -54) -> (-17, -54)
  line L2 (20, -43) -> (20, -51)
  line L3 (-17, -40) -> (17, -40)
  line L4 (-20, -51) -> (-20, -43)
  line L5 (3, -50.5) -> (-3, -50.5)
  line L6 (4.5, -45) -> (4.5, -49)
  line L7 (-3, -43.5) -> (3, -43.5)
  line L8 (-4.5, -49) -> (-4.5, -45)
  arc A1 centre (17, -51) radius 3 clockwise from (20, -51) to (17, -54)
  arc A2 centre (17, -43) radius 3 clockwise from (17, -40) to (20, -43)
  arc A3 centre (-17, -43) radius 3 clockwise from (-20, -43) to (-17, -40)
  arc A4 centre (-17, -51) radius 3 clockwise from (-17, -54) to (-20, -51)
  arc A5 centre (3, -49) radius 1.5 clockwise from (4.5, -49) to (3, -50.5)
  arc A6 centre (3, -45) radius 1.5 clockwise from (3, -43.5) to (4.5, -45)
  arc A7 centre (-3, -45) radius 1.5 clockwise from (-4.5, -45) to (-3, -43.5)
  arc A8 centre (-3, -49) radius 1.5 clockwise from (-3, -50.5) to (-4.5, -49)
extrude "Extrude1" new body sketch "Front Switch Clamp Plate Sketch" blind 1.4 from offset 10.9
sketch "Front Switch Corner Guide Sketch" plane through (0, 0, 0) normal (0, 0, 1) x axis (1, 0, 0)
  line L1 (-6.65, -55) -> (-7.55, -55)
  line L2 (-6.2, -53.65) -> (-6.2, -54.55)
  line L3 (-7.55, -53.2) -> (-6.65, -53.2)
  line L4 (-8, -54.55) -> (-8, -53.65)
  arc A1 centre (-6.65, -54.55) radius 0.45 clockwise from (-6.2, -54.55) to (-6.65, -55)
  arc A2 centre (-6.65, -53.65) radius 0.45 clockwise from (-6.65, -53.2) to (-6.2, -53.65)
  arc A3 centre (-7.55, -53.65) radius 0.45 clockwise from (-8, -53.65) to (-7.55, -53.2)
  arc A4 centre (-7.55, -54.55) radius 0.45 clockwise from (-7.55, -55) to (-8, -54.55)
extrude "Extrude2" add sketch "Front Switch Corner Guide Sketch" blind 7.25 from offset 3.65
sketch "Front Switch Corner Guide Sketch (1)" plane through (0, 0, 0) normal (0, 0, 1) x axis (1, 0, 0)
  line L1 (-6.65, -40.8) -> (-7.55, -40.8)
  line L2 (-6.2, -39.45) -> (-6.2, -40.35)
  line L3 (-7.55, -39) -> (-6.65, -39)
  line L4 (-8, -40.35) -> (-8, -39.45)
  arc A1 centre (-6.65, -40.35) radius 0.45 clockwise from (-6.2, -40.35) to (-6.65, -40.8)
  arc A2 centre (-6.65, -39.45) radius 0.45 clockwise from (-6.65, -39) to (-6.2, -39.45)
  arc A3 centre (-7.55, -39.45) radius 0.45 clockwise from (-8, -39.45) to (-7.55, -39)
  arc A4 centre (-7.55, -40.35) radius 0.45 clockwise from (-7.55, -40.8) to (-8, -40.35)
extrude "Extrude3" add sketch "Front Switch Corner Guide Sketch (1)" blind 7.25 from offset 3.65
sketch "Front Switch Corner Guide Sketch (2)" plane through (0, 0, 0) normal (0, 0, 1) x axis (1, 0, 0)
  line L1 (7.55, -55) -> (6.65, -55)
  line L2 (8, -53.65) -> (8, -54.55)
  line L3 (6.65, -53.2) -> (7.55, -53.2)
  line L4 (6.2, -54.55) -> (6.2, -53.65)
  arc A1 centre (7.55, -54.55) radius 0.45 clockwise from (8, -54.55) to (7.55, -55)
  arc A2 centre (7.55, -53.65) radius 0.45 clockwise from (7.55, -53.2) to (8, -53.65)
  arc A3 centre (6.65, -53.65) radius 0.45 clockwise from (6.2, -53.65) to (6.65, -53.2)
  arc A4 centre (6.65, -54.55) radius 0.45 clockwise from (6.65, -55) to (6.2, -54.55)
extrude "Extrude4" add sketch "Front Switch Corner Guide Sketch (2)" blind 7.25 from offset 3.65
sketch "Front Switch Corner Guide Sketch (3)" plane through (0, 0, 0) normal (0, 0, 1) x axis (1, 0, 0)
  line L1 (7.55, -40.8) -> (6.65, -40.8)
  line L2 (8, -39.45) -> (8, -40.35)
  line L3 (6.65, -39) -> (7.55, -39)
  line L4 (6.2, -40.35) -> (6.2, -39.45)
  arc A1 centre (7.55, -40.35) radius 0.45 clockwise from (8, -40.35) to (7.55, -40.8)
  arc A2 centre (7.55, -39.45) radius 0.45 clockwise from (7.55, -39) to (8, -39.45)
  arc A3 centre (6.65, -39.45) radius 0.45 clockwise from (6.2, -39.45) to (6.65, -39)
  arc A4 centre (6.65, -40.35) radius 0.45 clockwise from (6.65, -40.8) to (6.2, -40.35)
extrude "Extrude5" add sketch "Front Switch Corner Guide Sketch (3)" blind 7.25 from offset 3.65
sketch "Front Switch Clamp M2 Clearance Sketch" plane through (0, 0, 0) normal (0, 0, 1) x axis (1, 0, 0)
  circle C1 centre (-17, -47) radius 1.3
extrude "Extrude6" cut sketch "Front Switch Clamp M2 Clearance Sketch" blind 2.2 from offset 10.5
sketch "Front Switch Clamp M2 Clearance Sketch (1)" plane through (0, 0, 0) normal (0, 0, 1) x axis (1, 0, 0)
  circle C1 centre (17, -47) radius 1.3
extrude "Extrude7" cut sketch "Front Switch Clamp M2 Clearance Sketch (1)" blind 2.2 from offset 10.5
sketch "Tolerance Coupon Base Sketch" plane through (0, 0, 0) normal (0, 0, 1) x axis (1, 0, 0)
  line L1 (27, -12) -> (-27, -12)
  line L2 (30, 9) -> (30, -9)
  line L3 (-27, 12) -> (27, 12)
  line L4 (-30, -9) -> (-30, 9)
  arc A1 centre (27, -9) radius 3 clockwise from (30, -9) to (27, -12)
  arc A2 centre (27, 9) radius 3 clockwise from (27, 12) to (30, 9)
  arc A3 centre (-27, 9) radius 3 clockwise from (-30, 9) to (-27, 12)
  arc A4 centre (-27, -9) radius 3 clockwise from (-27, -12) to (-30, -9)
extrude "Extrude1" new body sketch "Tolerance Coupon Base Sketch" blind 2.4 bodies "Prototype Tolerance Coupon"
sketch "Lens Fit Hole 5.2 mm Sketch" plane through (0, 0, 0) normal (0, 0, 1) x axis (1, 0, 0)
  circle C1 centre (-22, 2.5) radius 2.6
extrude "Extrude2" cut sketch "Lens Fit Hole 5.2 mm Sketch" blind 2.7 from offset -0.1
sketch "Lens Fit Hole 5.3 mm Sketch" plane through (0, 0, 0) normal (0, 0, 1) x axis (1, 0, 0)
  circle C1 centre (-14, 2.5) radius 2.65
extrude "Extrude3" cut sketch "Lens Fit Hole 5.3 mm Sketch" blind 2.7 from offset -0.1
sketch "Lens Fit Hole 5.4 mm Sketch" plane through (0, 0, 0) normal (0, 0, 1) x axis (1, 0, 0)
  circle C1 centre (-6, 2.5) radius 2.7
extrude "Extrude4" cut sketch "Lens Fit Hole 5.4 mm Sketch" blind 2.7 from offset -0.1
sketch "Actuator Slot 2.6 mm Sketch" plane through (0, 0, 0) normal (0, 0, 1) x axis (1, 0, 0)
  line L1 (7.05, -2.5) -> (6.95, -2.5)
  line L2 (8.3, 4.25) -> (8.3, -1.25)
  line L3 (6.95, 5.5) -> (7.05, 5.5)
  line L4 (5.7, -1.25) -> (5.7, 4.25)
  arc A1 centre (7.05, -1.25) radius 1.25 clockwise from (8.3, -1.25) to (7.05, -2.5)
  arc A2 centre (7.05, 4.25) radius 1.25 clockwise from (7.05, 5.5) to (8.3, 4.25)
  arc A3 centre (6.95, 4.25) radius 1.25 clockwise from (5.7, 4.25) to (6.95, 5.5)
  arc A4 centre (6.95, -1.25) radius 1.25 clockwise from (6.95, -2.5) to (5.7, -1.25)
extrude "Extrude5" cut sketch "Actuator Slot 2.6 mm Sketch" blind 2.7 from offset -0.1
sketch "Actuator Slot 2.8 mm Sketch" plane through (0, 0, 0) normal (0, 0, 1) x axis (1, 0, 0)
  line L1 (16.05, -2.5) -> (15.95, -2.5)
  line L2 (17.4, 4.15) -> (17.4, -1.15)
  line L3 (15.95, 5.5) -> (16.05, 5.5)
  line L4 (14.6, -1.15) -> (14.6, 4.15)
  arc A1 centre (16.05, -1.15) radius 1.35 clockwise from (17.4, -1.15) to (16.05, -2.5)
  arc A2 centre (16.05, 4.15) radius 1.35 clockwise from (16.05, 5.5) to (17.4, 4.15)
  arc A3 centre (15.95, 4.15) radius 1.35 clockwise from (14.6, 4.15) to (15.95, 5.5)
  arc A4 centre (15.95, -1.15) radius 1.35 clockwise from (15.95, -2.5) to (14.6, -1.15)
extrude "Extrude6" cut sketch "Actuator Slot 2.8 mm Sketch" blind 2.7 from offset -0.1
sketch "Actuator Slot 3.0 mm Sketch" plane through (0, 0, 0) normal (0, 0, 1) x axis (1, 0, 0)
  line L1 (25.05, -2.5) -> (24.95, -2.5)
  line L2 (26.5, 4.05) -> (26.5, -1.05)
  line L3 (24.95, 5.5) -> (25.05, 5.5)
  line L4 (23.5, -1.05) -> (23.5, 4.05)
  arc A1 centre (25.05, -1.05) radius 1.45 clockwise from (26.5, -1.05) to (25.05, -2.5)
  arc A2 centre (25.05, 4.05) radius 1.45 clockwise from (25.05, 5.5) to (26.5, 4.05)
  arc A3 centre (24.95, 4.05) radius 1.45 clockwise from (23.5, 4.05) to (24.95, 5.5)
  arc A4 centre (24.95, -1.05) radius 1.45 clockwise from (24.95, -2.5) to (23.5, -1.05)
extrude "Extrude7" cut sketch "Actuator Slot 3.0 mm Sketch" blind 2.7 from offset -0.1
sketch "Grille Process Hole 2.20 mm Sketch" plane through (0, 0, 0) normal (0, 0, 1) x axis (1, 0, 0)
  circle C1 centre (-8, -7) radius 1.1
extrude "Extrude8" cut sketch "Grille Process Hole 2.20 mm Sketch" blind 2.7 from offset -0.1
sketch "Grille Process Hole 2.20 mm Sketch (1)" plane through (0, 0, 0) normal (0, 0, 1) x axis (1, 0, 0)
  circle C1 centre (-4.8, -7) radius 1.1
extrude "Extrude9" cut sketch "Grille Process Hole 2.20 mm Sketch (1)" blind 2.7 from offset -0.1
sketch "Grille Process Hole 1.80 mm Sketch" plane through (0, 0, 0) normal (0, 0, 1) x axis (1, 0, 0)
  circle C1 centre (4, -7) radius 0.9
extrude "Extrude10" cut sketch "Grille Process Hole 1.80 mm Sketch" blind 2.7 from offset -0.1
sketch "Grille Process Hole 1.40 mm Sketch" plane through (0, 0, 0) normal (0, 0, 1) x axis (1, 0, 0)
  circle C1 centre (11, -7) radius 0.7
extrude "Extrude11" cut sketch "Grille Process Hole 1.40 mm Sketch" blind 2.7 from offset -0.1
sketch "Flex Rib 1.0 mm Sketch" plane through (0, 0, 0) normal (0, 0, 1) x axis (1, 0, 0)
  line L1 (-13.8, 11) -> (-16.2, 11)
  line L2 (-13, 24.2) -> (-13, 11.8)
  line L3 (-16.2, 25) -> (-13.8, 25)
  line L4 (-17, 11.8) -> (-17, 24.2)
  arc A1 centre (-13.8, 11.8) radius 0.8 clockwise from (-13, 11.8) to (-13.8, 11)
  arc A2 centre (-13.8, 24.2) radius 0.8 clockwise from (-13.8, 25) to (-13, 24.2)
  arc A3 centre (-16.2, 24.2) radius 0.8 clockwise from (-17, 24.2) to (-16.2, 25)
  arc A4 centre (-16.2, 11.8) radius 0.8 clockwise from (-16.2, 11) to (-17, 11.8)
extrude "Extrude12" add sketch "Flex Rib 1.0 mm Sketch" blind 1
sketch "Flex Rib 1.2 mm Sketch" plane through (0, 0, 0) normal (0, 0, 1) x axis (1, 0, 0)
  line L1 (1.2, 11) -> (-1.2, 11)
  line L2 (2, 24.2) -> (2, 11.8)
  line L3 (-1.2, 25) -> (1.2, 25)
  line L4 (-2, 11.8) -> (-2, 24.2)
  arc A1 centre (1.2, 11.8) radius 0.8 clockwise from (2, 11.8) to (1.2, 11)
  arc A2 centre (1.2, 24.2) radius 0.8 clockwise from (1.2, 25) to (2, 24.2)
  arc A3 centre (-1.2, 24.2) radius 0.8 clockwise from (-2, 24.2) to (-1.2, 25)
  arc A4 centre (-1.2, 11.8) radius 0.8 clockwise from (-1.2, 11) to (-2, 11.8)
extrude "Extrude13" add sketch "Flex Rib 1.2 mm Sketch" blind 1.2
